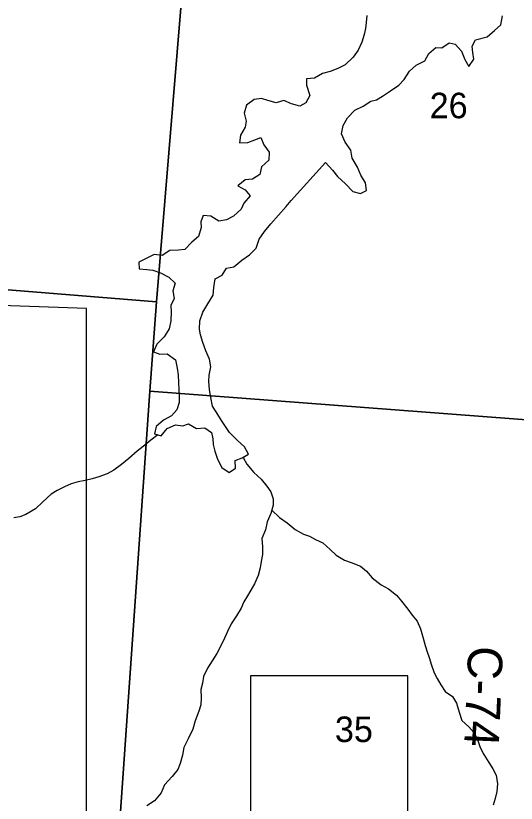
# Model space of a CAD drawing. Extents: x 1715311 to 2083412, y 146837 to 553079.
# Drawn here: x 1909729 to 1914063, y 377110 to 383925 of the extents above; entities that cross this region are included whole.
import ezdxf

# ---------------------------------------------------------------- set-up
doc = ezdxf.new("R2010")
doc.units = 0
for name, color, linetype in [('GM_X_Corporation', 7, 'Continuous'), ('GM_X_County_Road_Text', 7, 'Continuous'), ('GM_X_Major_Lake', 7, 'Continuous'), ('GM_X_Minor_River', 7, 'Continuous'), ('GM_X_Section', 7, 'Continuous'), ('GM_X_Section_Text', 7, 'Continuous')]:
    doc.layers.add(name, color=color, linetype=linetype)

msp = doc.modelspace()

# ---------------------------------------------------------------- linework, layer by layer
at = {"layer": 'GM_X_Corporation'}
for points in [[(1910343.2, 377031.2), (1910343.2, 381391.4), (1909603.6, 381417.2)], [(1913123.1, 376971.3), (1913123.1, 378211.4), (1911763.1, 378211.3), (1911762.1, 375222.1)]]:
    msp.add_lwpolyline(points, dxfattribs=at)
at = {"layer": 'GM_X_Major_Lake'}
msp.add_line((1912114.5, 382326.7), (1912411, 382654.9), dxfattribs=at)
for points in [[(1912768.7, 383926), (1912762.2, 383865.9), (1912757.8, 383815.9), (1912745.4, 383761.9), (1912726.9, 383696), (1912694.4, 383628.1), (1912649.9, 383566.4), (1912581.4, 383500.8), (1912519.1, 383469.2), (1912452.9, 383441.7), (1912384.7, 383424.1), (1912316.4, 383384.6), (1912246.3, 383379.1), (1912247.9, 383323), (1912275.3, 383234.7), (1912240.8, 383172.9), (1912188.6, 383143.2), (1912116.7, 383161.8), (1912050.8, 383190.3), (1911984.7, 383172.8), (1911912.8, 383191.3), (1911856.9, 383209.8), (1911792.8, 383200.2), (1911726.4, 383150.6), (1911707.9, 383080.7), (1911723.4, 383012.5), (1911717, 382960.5), (1911674.4, 382892.7), (1911668, 382826.6), (1911738, 382828.1), (1911800.2, 382851.7), (1911850.4, 382871.4), (1911877.9, 382807.1), (1911923.5, 382744.6), (1911921, 382676.6), (1911856.5, 382617), (1911844, 382551), (1911779.7, 382511.4), (1911715.6, 382503.9), (1911653.2, 382452.2), (1911714.9, 382417.8), (1911758.6, 382365.4), (1911704.1, 382303.7), (1911681.7, 382251.8), (1911615.2, 382190.2), (1911552.9, 382158.6), (1911486.8, 382147.1), (1911419.1, 382191.6), (1911353.1, 382196.1), (1911332.7, 382142.2), (1911334.3, 382092.1), (1911311.7, 382014.2), (1911255.3, 381964.5), (1911192.9, 381902.9), (1911138.8, 381897.3), (1911062.7, 381893.9), (1910998.4, 381850.3), (1910928.4, 381858.8), (1910858.1, 381825.3), (1910793.9, 381793.7), (1910799.4, 381735.6), (1910865.4, 381729.1), (1910917.4, 381722.7), (1910983.2, 381700.2)], [(1912411, 382654.9), (1912472.6, 382588.4), (1912514.2, 382534), (1912585.7, 382469.4), (1912647.3, 382404.8), (1912713.2, 382386.3), (1912765.4, 382414), (1912757.9, 382478.1), (1912716.4, 382546.5), (1912688.9, 382614.8), (1912641.4, 382691.3), (1912631.9, 382761.4), (1912580.4, 382831.9), (1912548.9, 382902.2), (1912563.5, 382974.2), (1912602, 383042), (1912666.5, 383107.6), (1912738.8, 383143.2), (1912803.2, 383184.8), (1912853.3, 383198.4), (1912903.5, 383230.1), (1912973.9, 383275.6), (1913046.3, 383323.1), (1913092.7, 383374.9), (1913139.3, 383444.6), (1913197.7, 383498.2), (1913270, 383535.8), (1913306.5, 383599.6), (1913366.9, 383649.2), (1913418.9, 383648.8), (1913483.3, 383690.4), (1913535.2, 383678), (1913588.8, 383617.5), (1913616.3, 383547.2), (1913651.8, 383484.9), (1913694.3, 383548.6), (1913686.7, 383606.8), (1913681.1, 383660.9), (1913709.6, 383716.8), (1913809.8, 383744.1), (1913874.2, 383797.7), (1913928.6, 383847.3), (1913945.2, 383925.3)], [(1910983.2, 381700.2), (1911055, 381661.6), (1911110.7, 381611.1), (1911088.1, 381545.2), (1911101.7, 381479), (1911073.2, 381417.1), (1911074.8, 381363), (1911072.2, 381285), (1911057.7, 381215), (1911015.2, 381147.2), (1910950.6, 381083.6), (1910922.1, 381015.7), (1910976, 380997.3), (1911040.1, 380998.8), (1911111.7, 380948.2), (1911127.2, 380874), (1911134.8, 380817.8), (1911138.2, 380747.7), (1911141.8, 380689.6), (1911143.4, 380631.5), (1911143, 380579.4), (1911124.5, 380513.5), (1911078.1, 380461.7), (1911009.8, 380424.2), (1910945.3, 380370.6), (1910930.9, 380306.6), (1910988.8, 380290.2), (1911039.3, 380353.9), (1911111.5, 380383.4), (1911175.5, 380376.9), (1911225.7, 380394.6), (1911295.4, 380354), (1911367.5, 380359.5), (1911423.2, 380317), (1911434.8, 380264.8), (1911438.4, 380214.7), (1911452, 380156.5), (1911475.5, 380086.3), (1911513, 380015.9), (1911576.7, 379973.4), (1911631, 380009), (1911629.5, 380075.1), (1911689.7, 380098.7), (1911743.9, 380130.3), (1911710.4, 380194.7), (1911648.8, 380249.2), (1911581.3, 380317.8), (1911545.6, 380370.2), (1911510, 380422.5), (1911480.4, 380474.8), (1911432.9, 380547.2), (1911417.4, 380621.5), (1911405.9, 380687.6), (1911402.5, 380763.8), (1911404.9, 380815.8), (1911417.4, 380885.8), (1911407.9, 380954), (1911376.4, 381024.3), (1911348.9, 381096.6), (1911329.4, 381162.9), (1911319.8, 381213), (1911322.3, 381285.1), (1911348.9, 381359), (1911391.5, 381432.8), (1911438, 381506.5), (1911444.5, 381574.6), (1911457.1, 381648.6), (1911515.4, 381680.2), (1911553.8, 381742), (1911617.9, 381751.6), (1911686.4, 381809.1), (1911752.8, 381856.7), (1911811.2, 381914.4), (1911837.8, 381990.3), (1911882.3, 382058), (1911938.9, 382125.7), (1912005.4, 382199.3), (1912070, 382274.9), (1912114.5, 382326.7)]]:
    msp.add_lwpolyline(points, dxfattribs=at)
at = {"layer": 'GM_X_Minor_River'}
for points in [[(1910959.2, 380298.6), (1910898.8, 380253.4), (1910832.4, 380195.8), (1910780.2, 380158.1), (1910709.9, 380092.5), (1910645.6, 380040.8), (1910577.3, 379991.2), (1910521.2, 379961.6), (1910449, 379934), (1910391, 379918.4), (1910331, 379902.8), (1910268.9, 379891.2), (1910208.9, 379873.5), (1910152.8, 379847.9), (1910086.6, 379816.3), (1910036.5, 379784.6), (1909964.1, 379717), (1909901.7, 379657.3), (1909817.5, 379609.8), (1909763.4, 379588.2), (1909711.4, 379580.5)], [(1911697.7, 380103.4), (1911730.5, 380045.6), (1911791.9, 379973.2), (1911855.5, 379914.7), (1911903, 379854.3), (1911938.6, 379804), (1911958.2, 379743.8), (1911957.8, 379689.7), (1911937.3, 379617.8), (1911906.9, 379545.9), (1911890.4, 379475.9), (1911859.9, 379400), (1911865.4, 379327.9), (1911867, 379263.8), (1911854.6, 379201.8), (1911844.2, 379147.9), (1911827.8, 379079.9), (1911797.3, 379008), (1911736.7, 378904.3), (1911704.4, 378852.4), (1911680, 378798.5), (1911639.6, 378732.7), (1911595.2, 378662.9), (1911562.8, 378595.1), (1911526.2, 378513.2), (1911471.6, 378405.4), (1911390.8, 378277.8), (1911356.3, 378206), (1911345.9, 378148), (1911331.6, 378094), (1911335.1, 378021.9), (1911330.7, 377961.8), (1911314.3, 377907.9), (1911281.8, 377822), (1911261.3, 377752.1), (1911222.8, 377666.2), (1911184.3, 377592.4), (1911171.9, 377524.4), (1911153.4, 377454.4), (1911133.1, 377402.5), (1911082.7, 377340.7), (1911018.3, 377269.1), (1910989.8, 377201.2), (1910929.4, 377129.5), (1910865.2, 377085.9)], [(1911945.5, 379646.5), (1912013, 379583.2), (1912078.6, 379536.8), (1912148.2, 379478.2), (1912219.8, 379439.7), (1912273.7, 379421.3), (1912325.4, 379393), (1912389.1, 379362.5), (1912452.7, 379306), (1912504.3, 379255.6), (1912575.9, 379213.1), (1912633.7, 379194.7), (1912713.4, 379162.1), (1912765.1, 379119.7), (1912814.6, 379059.3), (1912894.1, 379000.8), (1912957.8, 378964.3), (1913025.4, 378911.8), (1913069, 378859.4), (1913124.5, 378789), (1913162.1, 378738.7), (1913205.7, 378684.3), (1913235.2, 378618.1), (1913256.6, 378537.8), (1913274.2, 378475.6), (1913291.8, 378421.5), (1913307.4, 378371.3), (1913328.9, 378305.1), (1913352.5, 378238.8), (1913378.1, 378188.6), (1913409.7, 378134.3), (1913447.3, 378076), (1913510.9, 378033.6), (1913544.5, 377975.3), (1913567.9, 377897), (1913591.4, 377826.8), (1913652.9, 377770.3), (1913698.5, 377718), (1913730.1, 377651.7), (1913749.6, 377593.5), (1913781.2, 377531.2), (1913824.7, 377462.8), (1913860.3, 377408.5), (1913887.9, 377352.3), (1913899.3, 377278.1), (1913894.9, 377210), (1913880.5, 377150.1), (1913862.1, 377092.1)]]:
    msp.add_lwpolyline(points, dxfattribs=at)
at = {"layer": 'GM_X_Section'}
for points in [[(1911385.5, 386748.1), (1911340.4, 386192.2), (1910948.6, 381448.6), (1905481, 381889.8), (1905843.9, 387183.5)], [(1916071.7, 385628.4), (1915630.8, 380316.9), (1910889, 380676.6), (1910948.6, 381448.6), (1911340.4, 386192.2)], [(1905481, 381889.8), (1910948.6, 381448.6), (1910889, 380676.6), (1910518, 375342.9), (1909680, 375404.7), (1904842.4, 375808.6)], [(1910889, 380676.6), (1915630.8, 380316.9), (1915275.7, 374963.1), (1910518, 375342.9)]]:
    msp.add_lwpolyline(points, close=True, dxfattribs=at)

# ---------------------------------------------------------------- texts
at = {"layer": 'GM_X_County_Road_Text'}
msp.add_text('C-74', height=300, rotation=267.59978, dxfattribs=at).set_placement((1913648.3, 378474.8))
at = {"layer": 'GM_X_Section_Text'}
for s, p in [('26', (1913313.3, 383038.1)), ('35', (1912492.7, 377639.3))]:
    msp.add_text(s, height=221, rotation=0.00001, dxfattribs=at).set_placement(p)

doc.saveas('drawing.dxf')
